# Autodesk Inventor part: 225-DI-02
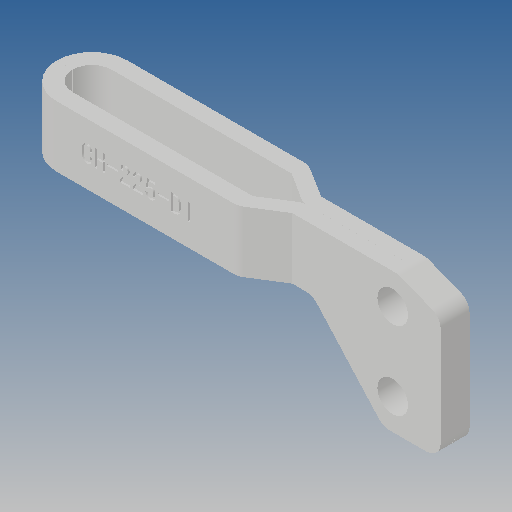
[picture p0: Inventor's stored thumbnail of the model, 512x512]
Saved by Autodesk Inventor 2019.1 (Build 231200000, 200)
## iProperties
Created: 2013-01
Part Number: 225-DI-02
Material: Ogólny
Document SubType Name: Modeling
Designer: CADENGINEERING4
Density: 1 g/cm^3
Appearance: Domyślna
Author: CADENGINEERING4
Revision Number: ÈÎºÎ
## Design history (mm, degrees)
feature "ÇÐ³ý-À­Éì2"
feature "ÇÐ³ý-À­Éì4"
node "Bryła1"
node "Bryła2"
